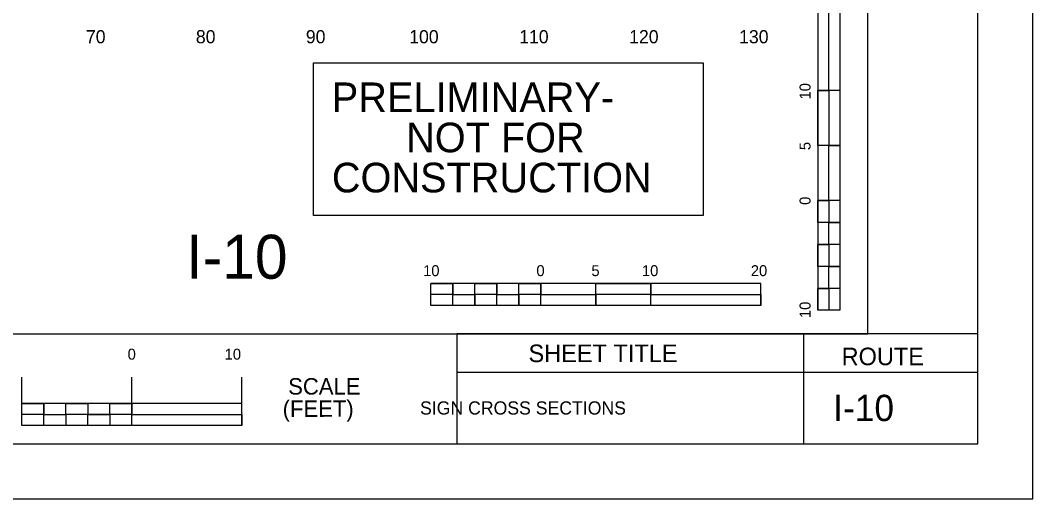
# Model space of a CAD drawing. Extents: x 1797809 to 2198143, y 249608 to 1237864.
# Drawn here: x 2194760.6 to 2194852.7, y 1237118 to 1237161.6 of the extents above; entities that cross this region are included whole.
import ezdxf

# ---------------------------------------------------------------- set-up
doc = ezdxf.new("R2010")
doc.units = 0
for name, color, linetype in [('10', 7, 'Continuous'), ('29', 7, 'Continuous'), ('GSCOLORFILL', 7, 'Continuous'), ('GSDIMS', 7, 'Continuous'), ('GSOUTLINE', 7, 'Continuous'), ('GSSHT', 7, 'Continuous'), ('Level 1', 7, 'Continuous'), ('Level 30', 7, 'Continuous'), ('Level 33', 7, 'Continuous'), ('Level 45', 7, 'Continuous'), ('UGUT', 7, 'Continuous')]:
    doc.layers.add(name, color=color, linetype=linetype)

msp = doc.modelspace()

# ---------------------------------------------------------------- linework, layer by layer
at = {"layer": '29'}
for p, q in [((2194833.16, 1237165.195), (2194833.16, 1237135.195)), ((2194833.16, 1237165.195), (2194833.16, 1237135.195)), ((2194835.16, 1237165.195), (2194835.16, 1237155.195)), ((2194835.16, 1237165.195), (2194835.16, 1237135.195)), ((2194835.16, 1237165.195), (2194835.16, 1237155.195)), ((2194835.16, 1237165.195), (2194835.16, 1237135.195)), ((2194834.16, 1237155.195), (2194833.16, 1237155.195)), ((2194835.16, 1237155.195), (2194833.16, 1237155.195)), ((2194834.16, 1237155.195), (2194833.16, 1237155.195)), ((2194835.16, 1237155.195), (2194833.16, 1237155.195)), ((2194834.16, 1237155.195), (2194834.16, 1237150.195)), ((2194834.16, 1237155.195), (2194834.16, 1237150.195)), ((2194835.16, 1237150.195), (2194833.16, 1237150.195)), ((2194835.16, 1237150.195), (2194833.16, 1237150.195)), ((2194835.16, 1237150.195), (2194834.16, 1237150.195)), ((2194835.16, 1237150.195), (2194834.16, 1237150.195)), ((2194835.16, 1237150.195), (2194835.16, 1237145.195)), ((2194835.16, 1237150.195), (2194835.16, 1237145.195)), ((2194834.16, 1237145.195), (2194833.16, 1237145.195)), ((2194835.16, 1237145.195), (2194833.16, 1237145.195)), ((2194834.16, 1237145.195), (2194833.16, 1237145.195)), ((2194835.16, 1237145.195), (2194833.16, 1237145.195)), ((2194834.16, 1237145.195), (2194834.16, 1237143.195)), ((2194834.16, 1237145.195), (2194834.16, 1237143.195)), ((2194835.16, 1237143.195), (2194834.16, 1237143.195)), ((2194835.16, 1237143.195), (2194834.16, 1237143.195)), ((2194835.16, 1237143.195), (2194835.16, 1237141.195)), ((2194835.16, 1237143.195), (2194835.16, 1237141.195)), ((2194834.16, 1237141.195), (2194833.16, 1237141.195)), ((2194834.16, 1237141.195), (2194833.16, 1237141.195)), ((2194834.16, 1237141.195), (2194834.16, 1237139.195)), ((2194834.16, 1237141.195), (2194834.16, 1237139.195)), ((2194835.16, 1237139.195), (2194834.16, 1237139.195)), ((2194835.16, 1237139.195), (2194834.16, 1237139.195)), ((2194835.16, 1237139.195), (2194835.16, 1237137.195)), ((2194835.16, 1237139.195), (2194835.16, 1237137.195)), ((2194827.956, 1237137.63), (2194797.956, 1237137.63)), ((2194797.956, 1237135.63), (2194797.956, 1237137.63)), ((2194827.956, 1237137.63), (2194797.956, 1237137.63)), ((2194797.956, 1237135.63), (2194797.956, 1237137.63)), ((2194799.956, 1237136.63), (2194799.956, 1237137.63)), ((2194799.956, 1237136.63), (2194799.956, 1237137.63)), ((2194803.956, 1237136.63), (2194803.956, 1237137.63)), ((2194803.956, 1237136.63), (2194803.956, 1237137.63)), ((2194807.956, 1237136.63), (2194807.956, 1237137.63)), ((2194807.956, 1237135.63), (2194807.956, 1237137.63)), ((2194807.956, 1237136.63), (2194807.956, 1237137.63)), ((2194807.956, 1237135.63), (2194807.956, 1237137.63)), ((2194812.956, 1237135.63), (2194812.956, 1237137.63)), ((2194812.956, 1237135.63), (2194812.956, 1237137.63)), ((2194817.956, 1237136.63), (2194817.956, 1237137.63)), ((2194817.956, 1237135.63), (2194817.956, 1237137.63)), ((2194817.956, 1237136.63), (2194817.956, 1237137.63)), ((2194817.956, 1237135.63), (2194817.956, 1237137.63)), ((2194827.956, 1237135.63), (2194827.956, 1237137.63)), ((2194827.956, 1237135.63), (2194827.956, 1237137.63)), ((2194834.16, 1237137.195), (2194833.16, 1237137.195)), ((2194834.16, 1237137.195), (2194833.16, 1237137.195)), ((2194834.16, 1237137.195), (2194834.16, 1237135.195)), ((2194834.16, 1237137.195), (2194834.16, 1237135.195)), ((2194799.956, 1237136.63), (2194797.956, 1237136.63)), ((2194799.956, 1237136.63), (2194797.956, 1237136.63)), ((2194801.956, 1237135.63), (2194801.956, 1237136.63)), ((2194803.956, 1237136.63), (2194801.956, 1237136.63)), ((2194801.956, 1237135.63), (2194801.956, 1237136.63)), ((2194803.956, 1237136.63), (2194801.956, 1237136.63)), ((2194805.956, 1237135.63), (2194805.956, 1237136.63)), ((2194807.956, 1237136.63), (2194805.956, 1237136.63)), ((2194805.956, 1237135.63), (2194805.956, 1237136.63)), ((2194807.956, 1237136.63), (2194805.956, 1237136.63)), ((2194812.956, 1237135.63), (2194812.956, 1237136.63)), ((2194817.956, 1237136.63), (2194812.956, 1237136.63)), ((2194812.956, 1237135.63), (2194812.956, 1237136.63)), ((2194817.956, 1237136.63), (2194812.956, 1237136.63)), ((2194827.956, 1237135.63), (2194797.956, 1237135.63)), ((2194827.956, 1237135.63), (2194797.956, 1237135.63)), ((2194801.956, 1237135.63), (2194799.956, 1237135.63)), ((2194801.956, 1237135.63), (2194799.956, 1237135.63)), ((2194805.956, 1237135.63), (2194803.956, 1237135.63)), ((2194805.956, 1237135.63), (2194803.956, 1237135.63)), ((2194812.956, 1237135.63), (2194807.956, 1237135.63)), ((2194812.956, 1237135.63), (2194807.956, 1237135.63)), ((2194827.956, 1237135.63), (2194817.956, 1237135.63)), ((2194827.956, 1237135.63), (2194817.956, 1237135.63)), ((2194835.16, 1237135.195), (2194833.16, 1237135.195)), ((2194835.16, 1237135.195), (2194833.16, 1237135.195))]:
    msp.add_line(p, q, dxfattribs=at)
for points in [[(2194834.16, 1237155.195), (2194834.16, 1237165.195), (2194835.16, 1237165.195), (2194835.16, 1237155.195)], [(2194834.16, 1237155.195), (2194834.16, 1237165.195), (2194835.16, 1237165.195), (2194835.16, 1237155.195)], [(2194833.16, 1237150.195), (2194833.16, 1237155.195), (2194834.16, 1237155.195), (2194834.16, 1237150.195)], [(2194833.16, 1237150.195), (2194833.16, 1237155.195), (2194834.16, 1237155.195), (2194834.16, 1237150.195)], [(2194834.16, 1237145.195), (2194834.16, 1237150.195), (2194835.16, 1237150.195), (2194835.16, 1237145.195)], [(2194834.16, 1237145.195), (2194834.16, 1237150.195), (2194835.16, 1237150.195), (2194835.16, 1237145.195)], [(2194833.16, 1237143.195), (2194833.16, 1237145.195), (2194834.16, 1237145.195), (2194834.16, 1237143.195)], [(2194833.16, 1237143.195), (2194833.16, 1237145.195), (2194834.16, 1237145.195), (2194834.16, 1237143.195)], [(2194834.16, 1237141.195), (2194834.16, 1237143.195), (2194835.16, 1237143.195), (2194835.16, 1237141.195)], [(2194834.16, 1237141.195), (2194834.16, 1237143.195), (2194835.16, 1237143.195), (2194835.16, 1237141.195)], [(2194833.16, 1237139.195), (2194833.16, 1237141.195), (2194834.16, 1237141.195), (2194834.16, 1237139.195)], [(2194833.16, 1237139.195), (2194833.16, 1237141.195), (2194834.16, 1237141.195), (2194834.16, 1237139.195)], [(2194834.16, 1237137.195), (2194834.16, 1237139.195), (2194835.16, 1237139.195), (2194835.16, 1237137.195)], [(2194834.16, 1237137.195), (2194834.16, 1237139.195), (2194835.16, 1237139.195), (2194835.16, 1237137.195)], [(2194797.956, 1237137.63), (2194799.956, 1237137.63), (2194799.956, 1237136.63), (2194797.956, 1237136.63)], [(2194797.956, 1237137.63), (2194799.956, 1237137.63), (2194799.956, 1237136.63), (2194797.956, 1237136.63)], [(2194801.956, 1237137.63), (2194803.956, 1237137.63), (2194803.956, 1237136.63), (2194801.956, 1237136.63)], [(2194801.956, 1237137.63), (2194803.956, 1237137.63), (2194803.956, 1237136.63), (2194801.956, 1237136.63)], [(2194805.956, 1237137.63), (2194807.956, 1237137.63), (2194807.956, 1237136.63), (2194805.956, 1237136.63)], [(2194805.956, 1237137.63), (2194807.956, 1237137.63), (2194807.956, 1237136.63), (2194805.956, 1237136.63)], [(2194812.956, 1237137.63), (2194817.956, 1237137.63), (2194817.956, 1237136.63), (2194812.956, 1237136.63)], [(2194812.956, 1237137.63), (2194817.956, 1237137.63), (2194817.956, 1237136.63), (2194812.956, 1237136.63)], [(2194833.16, 1237135.195), (2194833.16, 1237137.195), (2194834.16, 1237137.195), (2194834.16, 1237135.195)], [(2194833.16, 1237135.195), (2194833.16, 1237137.195), (2194834.16, 1237137.195), (2194834.16, 1237135.195)], [(2194799.956, 1237136.63), (2194801.956, 1237136.63), (2194801.956, 1237135.63), (2194799.956, 1237135.63)], [(2194799.956, 1237136.63), (2194801.956, 1237136.63), (2194801.956, 1237135.63), (2194799.956, 1237135.63)], [(2194803.956, 1237136.63), (2194805.956, 1237136.63), (2194805.956, 1237135.63), (2194803.956, 1237135.63)], [(2194803.956, 1237136.63), (2194805.956, 1237136.63), (2194805.956, 1237135.63), (2194803.956, 1237135.63)], [(2194807.956, 1237136.63), (2194812.956, 1237136.63), (2194812.956, 1237135.63), (2194807.956, 1237135.63)], [(2194807.956, 1237136.63), (2194812.956, 1237136.63), (2194812.956, 1237135.63), (2194807.956, 1237135.63)], [(2194817.956, 1237136.63), (2194827.956, 1237136.63), (2194827.956, 1237135.63), (2194817.956, 1237135.63)], [(2194817.956, 1237136.63), (2194827.956, 1237136.63), (2194827.956, 1237135.63), (2194817.956, 1237135.63)]]:
    msp.add_lwpolyline(points, close=True, dxfattribs=at)
at = {"layer": 'GSCOLORFILL'}
for p, q in [((2194800.351, 1237123.036), (2194800.351, 1237133.046)), ((2194831.879, 1237123.036), (2194831.879, 1237133.046))]:
    msp.add_line(p, q, dxfattribs=at)
msp.add_lwpolyline([(2194525.191, 1237123.036), (2194847.691, 1237123.036), (2194847.691, 1237333.036), (2194525.191, 1237333.036)], close=True, dxfattribs=at)
at = {"layer": 'GSDIMS'}
for p, q in [((2194760.755, 1237124.7), (2194760.755, 1237129.1)), ((2194770.755, 1237124.7), (2194770.755, 1237129.1)), ((2194770.755, 1237124.7), (2194770.755, 1237129.1)), ((2194770.755, 1237124.7), (2194770.755, 1237129.1)), ((2194780.755, 1237124.7), (2194780.755, 1237129.1)), ((2194780.755, 1237126.7), (2194760.755, 1237126.7)), ((2194762.755, 1237125.7), (2194762.755, 1237126.7)), ((2194762.755, 1237125.7), (2194762.755, 1237126.7)), ((2194770.755, 1237125.7), (2194770.755, 1237126.7)), ((2194770.755, 1237125.7), (2194770.755, 1237126.7)), ((2194770.755, 1237125.7), (2194770.755, 1237126.7)), ((2194770.755, 1237125.7), (2194766.755, 1237125.7)), ((2194780.755, 1237124.7), (2194780.755, 1237125.7)), ((2194780.755, 1237124.7), (2194780.755, 1237125.7)), ((2194780.755, 1237124.7), (2194780.755, 1237125.7)), ((2194780.755, 1237124.7), (2194760.755, 1237124.7))]:
    msp.add_line(p, q, dxfattribs=at)
for points in [[(2194760.755, 1237126.7), (2194762.755, 1237126.7), (2194762.755, 1237125.7), (2194760.755, 1237125.7)], [(2194764.755, 1237126.7), (2194766.755, 1237126.7), (2194766.755, 1237125.7), (2194764.755, 1237125.7)], [(2194768.755, 1237126.7), (2194770.755, 1237126.7), (2194770.755, 1237125.7), (2194768.755, 1237125.7)], [(2194762.755, 1237125.7), (2194764.755, 1237125.7), (2194764.755, 1237124.7), (2194762.755, 1237124.7)], [(2194766.755, 1237125.7), (2194768.755, 1237125.7), (2194768.755, 1237124.7), (2194766.755, 1237124.7)], [(2194770.755, 1237125.7), (2194780.755, 1237125.7), (2194780.755, 1237124.7), (2194770.755, 1237124.7)]]:
    msp.add_lwpolyline(points, close=True, dxfattribs=at)
at = {"layer": 'GSOUTLINE'}
for p, q in [((2194800.351, 1237129.575), (2194831.879, 1237129.575)), ((2194831.879, 1237129.575), (2194847.691, 1237129.575))]:
    msp.add_line(p, q, dxfattribs=at)
at = {"layer": 'GSSHT'}
msp.add_lwpolyline([(2194512.691, 1237118.036), (2194852.691, 1237118.036), (2194852.691, 1237338.036), (2194512.691, 1237338.036)], close=True, dxfattribs=at)
at = {"layer": 'Level 30'}
msp.add_lwpolyline([(2194787.27, 1237157.719), (2194822.733, 1237157.719), (2194822.733, 1237143.824), (2194787.27, 1237143.824)], close=True, dxfattribs=at)
at = {"layer": 'Level 45'}
msp.add_lwpolyline([(2194537.688, 1237133.046), (2194837.688, 1237133.046), (2194837.688, 1237323.046), (2194537.688, 1237323.046)], close=True, dxfattribs=at)
at = {"layer": 'UGUT'}
msp.add_line((2194847.691, 1237133.046), (2194800.351, 1237133.046), dxfattribs=at)

# ---------------------------------------------------------------- texts
at = {"layer": '10'}
for s, p in [('70', (2194766.587, 1237159.506)), ('80', (2194776.587, 1237159.506)), ('90', (2194786.587, 1237159.506)), ('100', (2194795.987, 1237159.506)), ('110', (2194805.987, 1237159.506)), ('120', (2194815.987, 1237159.506)), ('130', (2194825.987, 1237159.506))]:
    msp.add_text(s, height=1.2, dxfattribs=at).set_placement(p)
at = {"layer": '29'}
for s, height, rotation, p in [('10', 0.9991, 90.0572, (2194832.486, 1237154.395)), ('10', 0.9991, 90.0572, (2194832.486, 1237154.395)), ('5', 1, 90.0572, (2194832.486, 1237149.78)), ('5', 1, 90.0572, (2194832.486, 1237149.78)), ('0', 1, 90.0572, (2194832.486, 1237144.795)), ('0', 1, 90.0572, (2194832.486, 1237144.795)), ('10', 0.9991, 0.0572, (2194797.256, 1237138.305)), ('10', 0.9991, 0.0572, (2194797.256, 1237138.305)), ('0', 1, 0.0572, (2194807.556, 1237138.304)), ('0', 1, 0.0572, (2194807.556, 1237138.304)), ('5', 0.999, 0.0572, (2194812.557, 1237138.304)), ('5', 0.999, 0.0572, (2194812.557, 1237138.304)), ('10', 0.9991, 0.0572, (2194817.156, 1237138.305)), ('10', 0.9991, 0.0572, (2194817.156, 1237138.305)), ('20', 0.9991, 0.0572, (2194827.056, 1237138.305)), ('20', 0.9991, 0.0572, (2194827.056, 1237138.305)), ('10', 0.9991, 90.0572, (2194832.486, 1237134.495)), ('10', 0.9991, 90.0572, (2194832.486, 1237134.495))]:
    msp.add_text(s, height=height, rotation=rotation, dxfattribs=at).set_placement(p)
at = {"layer": 'GSDIMS'}
for s, height, p in [('0', 1, (2194770.382, 1237130.7)), ('0', 1, (2194770.382, 1237130.7)), ('0', 1, (2194770.382, 1237130.7)), (' 10', 0.9991, (2194778.837, 1237130.7)), ('SCALE', 1.4994, (2194784.981, 1237127.522)), ('(FEET)', 1.4994, (2194784.48, 1237125.493))]:
    msp.add_text(s, height=height, rotation=0.0572, dxfattribs=at).set_placement(p)
at = {"layer": 'GSOUTLINE'}
for s, p in [('SHEET TITLE', (2194806.837, 1237130.478)), ('ROUTE', (2194835.31, 1237130.197))]:
    msp.add_text(s, height=1.6, dxfattribs=at).set_placement(p)
at = {"layer": 'Level 1'}
for s, height, p in [(' I-10 ', 2.4, (2194833.654, 1237125.106)), ('          SIGN CROSS SECTIONS          ', 1.2, (2194792.515, 1237125.706))]:
    msp.add_text(s, height=height, rotation=360, dxfattribs=at).set_placement(p)
at = {"layer": 'Level 30'}
for s, p in [('PRELIMINARY-', (2194788.947, 1237153.237)), ('NOT FOR', (2194795.702, 1237149.584)), ('CONSTRUCTION', (2194788.952, 1237145.931))]:
    msp.add_text(s, height=2.7, dxfattribs=at).set_placement(p)
at = {"layer": 'Level 33'}
msp.add_text('I-10', height=3.9977, rotation=360, dxfattribs=at).set_placement((2194775.712, 1237138.073))

doc.saveas('drawing.dxf')
